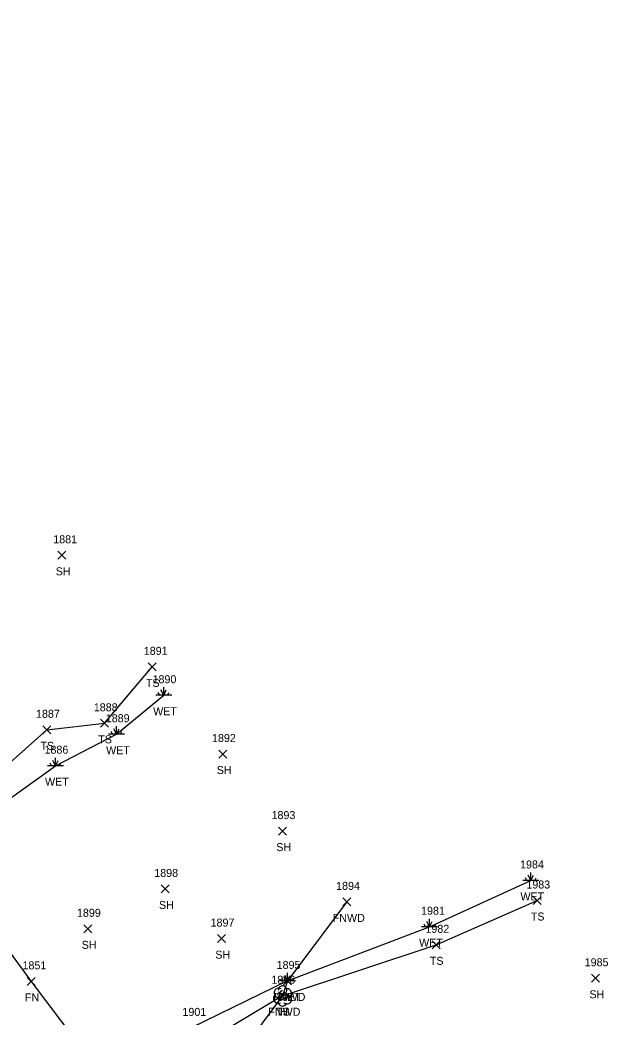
# Model space of a CAD drawing. Extents: x 1501299 to 1502485, y 381423 to 383765.
# Drawn here: x 1501516.8 to 1501663.7, y 383498.2 to 383747.3 of the extents above; entities that cross this region are included whole.
import ezdxf

# ---------------------------------------------------------------- set-up
doc = ezdxf.new("R2010")
doc.units = 0
for name, color, linetype in [('L_A', 7, 'Continuous'), ('L_I', 7, 'Continuous'), ('L_TIC', 7, 'Continuous'), ('LELB', 7, 'Continuous'), ('LFNC', 7, 'Continuous'), ('LTD', 7, 'Continuous'), ('LWET', 7, 'Continuous')]:
    doc.layers.add(name, color=color, linetype=linetype)

msp = doc.modelspace()

# ---------------------------------------------------------------- linework, layer by layer
at = {"layer": 'L_TIC'}
for points in [[(1501526.2, 383612.56), (1501528.2, 383614.56)], [(1501528.2, 383612.56), (1501526.2, 383614.56)], [(1501548.82, 383584.69), (1501550.82, 383586.69)], [(1501550.82, 383584.69), (1501548.82, 383586.69)], [(1501536.91, 383570.58), (1501538.91, 383572.58)], [(1501538.91, 383570.58), (1501536.91, 383572.58)], [(1501522.46, 383568.96), (1501524.46, 383570.96)], [(1501524.46, 383568.96), (1501522.46, 383570.96)], [(1501566.43, 383562.9), (1501568.43, 383564.9)], [(1501568.43, 383562.9), (1501566.43, 383564.9)], [(1501581.3, 383543.65), (1501583.3, 383545.65)], [(1501583.3, 383543.65), (1501581.3, 383545.65)], [(1501552, 383529.2), (1501554, 383531.2)], [(1501554, 383529.2), (1501552, 383531.2)], [(1501597.42, 383525.97), (1501599.42, 383527.97)], [(1501599.42, 383525.97), (1501597.42, 383527.97)], [(1501644.95, 383526.31), (1501646.95, 383528.31)], [(1501646.95, 383526.31), (1501644.95, 383528.31)], [(1501532.7, 383519.24), (1501534.7, 383521.24)], [(1501534.7, 383519.24), (1501532.7, 383521.24)], [(1501566.07, 383516.79), (1501568.07, 383518.79)], [(1501568.07, 383516.79), (1501566.07, 383518.79)], [(1501619.73, 383515.24), (1501621.73, 383517.24)], [(1501621.73, 383515.24), (1501619.73, 383517.24)], [(1501659.51, 383506.88), (1501661.51, 383508.88)], [(1501661.51, 383506.88), (1501659.51, 383508.88)], [(1501518.53, 383506.11), (1501520.53, 383508.11)], [(1501520.53, 383506.11), (1501518.53, 383508.11)], [(1501582.57, 383506.22), (1501584.57, 383508.22)], [(1501584.57, 383506.22), (1501582.57, 383508.22)], [(1501581.32, 383502.52), (1501583.32, 383504.52)], [(1501583.32, 383502.52), (1501581.32, 383504.52)], [(1501581.32, 383502.52), (1501583.32, 383504.52)], [(1501583.32, 383502.52), (1501581.32, 383504.52)], [(1501581.32, 383502.52), (1501583.32, 383504.52)], [(1501583.32, 383502.52), (1501581.32, 383504.52)]]:
    msp.add_lwpolyline(points, dxfattribs=at)
at = {"layer": 'LELB'}
for points in [[(1501492.24, 383541.02), (1501495.83, 383538.88), (1501505.86, 383554.33), (1501523.46, 383569.96), (1501537.91, 383571.58), (1501549.82, 383585.69)], [(1501582.32, 383503.52), (1501620.73, 383516.24), (1501645.95, 383527.31)], [(1501582.32, 383503.52), (1501563.19, 383491.98), (1501548.8, 383485.29), (1501544.05, 383474.54), (1501543.28, 383465.38), (1501557.45, 383442.58)]]:
    msp.add_lwpolyline(points, dxfattribs=at)
at = {"layer": 'LFNC'}
for points in [[(1501374.37, 383742.56), (1501382.94, 383727.21), (1501403.34, 383685.19), (1501409.51, 383674.58), (1501426.09, 383647.98), (1501436.22, 383631.2), (1501450.55, 383610.14), (1501477.09, 383568.96), (1501495.83, 383538.88), (1501500.46, 383533.1), (1501519.53, 383507.11), (1501541.76, 383477.61), (1501544.05, 383474.54), (1501551.42, 383461.96)], [(1501598.42, 383526.97), (1501583.57, 383507.22), (1501582.32, 383503.52), (1501551.42, 383461.96), (1501556.79, 383457.15), (1501570.08, 383443.83), (1501579.66, 383434.51), (1501590.93, 383422.47), (1501618.03, 383406.52), (1501631.82, 383398.73), (1501638.24, 383395.91), (1501648.8, 383391.86), (1501655.59, 383390.21)]]:
    msp.add_lwpolyline(points, dxfattribs=at)
at = {"layer": 'LTD'}
msp.add_line((1501582.32, 383503.52), (1501582.32, 383503.52), dxfattribs=at)
msp.add_line((1501582.32, 383503.52), (1501582.32, 383503.52), dxfattribs=at)
msp.add_arc((1501582.37, 383504.96), 1.05, 335.5272, 180.9563, dxfattribs=at)
for centre, major_axis, ratio, start_param, end_param in [((1501581.24, 383502.81), (0.58, -1.04), 0.959034, 3.141593, 6.283185), ((1501581.53, 383504.19), (1.21, -0.51), 0.895232, 1.570796, 4.712389), ((1501582.11, 383503.98), (-0.208, -0.792), 0.645439, 3.141593, 6.283185), ((1501582.82, 383503.35), (-0.5, 0.667), 0.989748, 3.141593, 6.283185), ((1501583.36, 383504.1), (-1.14, -0.48), 0.949671, 1.570796, 4.712389), ((1501582.32, 383502.02), (0.26, 1.06), 0.942809, 1.570796, 4.712389), ((1501581.86, 383502.77), (-0.625, -0.083), 0.423636, 0, 3.141593), ((1501583.32, 383502.69), (-1.09, 0.79), 0.841452, 1.570796, 4.712389)]:
    msp.add_ellipse(centre, major_axis=major_axis, ratio=ratio, start_param=start_param, end_param=end_param, dxfattribs=at)
at = {"layer": 'LWET'}
for p, q in [((1501554.66, 383578.59), (1501550.66, 383578.59)), ((1501551.66, 383578.59), (1501551.32, 383579.26)), ((1501552.66, 383578.59), (1501551.99, 383579.92)), ((1501552.66, 383578.59), (1501552.66, 383580.59)), ((1501552.66, 383578.59), (1501553.32, 383579.92)), ((1501553.66, 383578.59), (1501553.99, 383579.26)), ((1501542.9, 383568.85), (1501538.9, 383568.85)), ((1501539.9, 383568.85), (1501539.57, 383569.51)), ((1501540.9, 383568.85), (1501540.24, 383570.18)), ((1501540.9, 383568.85), (1501540.9, 383570.85)), ((1501540.9, 383568.85), (1501541.57, 383570.18)), ((1501541.9, 383568.85), (1501542.24, 383569.51)), ((1501524.64, 383560.99), (1501524.31, 383561.65)), ((1501525.64, 383560.99), (1501524.97, 383562.32)), ((1501525.64, 383560.99), (1501525.64, 383562.99)), ((1501525.64, 383560.99), (1501526.31, 383562.32)), ((1501526.64, 383560.99), (1501526.97, 383561.65)), ((1501527.64, 383560.99), (1501523.64, 383560.99)), ((1501644.39, 383532.32), (1501644.39, 383534.32)), ((1501646.39, 383532.32), (1501642.39, 383532.32)), ((1501643.39, 383532.32), (1501643.05, 383532.98)), ((1501644.39, 383532.32), (1501643.72, 383533.65)), ((1501644.39, 383532.32), (1501645.05, 383533.65)), ((1501645.39, 383532.32), (1501645.72, 383532.98)), ((1501618.08, 383520.76), (1501617.74, 383521.42)), ((1501619.08, 383520.76), (1501618.41, 383522.09)), ((1501619.08, 383520.76), (1501619.08, 383522.76)), ((1501619.08, 383520.76), (1501619.74, 383522.09)), ((1501620.08, 383520.76), (1501620.41, 383521.42)), ((1501621.08, 383520.76), (1501617.08, 383520.76)), ((1501583.57, 383507.22), (1501583.57, 383509.22)), ((1501583.57, 383507.22), (1501583.57, 383509.22)), ((1501585.57, 383507.22), (1501581.57, 383507.22)), ((1501585.57, 383507.22), (1501581.57, 383507.22)), ((1501582.57, 383507.22), (1501582.24, 383507.89)), ((1501582.57, 383507.22), (1501582.24, 383507.89)), ((1501583.57, 383507.22), (1501582.91, 383508.56)), ((1501583.57, 383507.22), (1501582.91, 383508.56)), ((1501583.57, 383507.22), (1501584.24, 383508.56)), ((1501583.57, 383507.22), (1501584.24, 383508.56)), ((1501584.57, 383507.22), (1501584.91, 383507.89)), ((1501584.57, 383507.22), (1501584.91, 383507.89))]:
    msp.add_line(p, q, dxfattribs=at)
for points in [[(1501368.35, 383738.78), (1501382.94, 383727.21), (1501398.82, 383737.57), (1501418, 383747.31), (1501440.05, 383727.46), (1501471.68, 383717.46), (1501494.57, 383699.38), (1501486.25, 383674.8), (1501474.27, 383650.63), (1501460.73, 383643.27), (1501445.76, 383639.75), (1501426.09, 383647.98), (1501433.24, 383627.92), (1501444.4, 383608.06), (1501471.74, 383565.71), (1501493.36, 383531.32), (1501500.46, 383533.1), (1501510.21, 383549.97), (1501525.64, 383560.99), (1501540.9, 383568.85), (1501552.66, 383578.59)], [(1501583.57, 383507.22), (1501619.08, 383520.76), (1501644.39, 383532.32)], [(1501583.57, 383507.22), (1501559.55, 383495.49), (1501547.97, 383488.67), (1501541.76, 383477.61), (1501540.15, 383463.77), (1501555.06, 383441.42)]]:
    msp.add_lwpolyline(points, dxfattribs=at)

# ---------------------------------------------------------------- texts
at = {"layer": 'L_A'}
for s, p in [('SH', (1501525.69, 383608.56)), ('TS', (1501548.23, 383580.69)), ('WET', (1501550.03, 383573.59)), ('TS', (1501536.32, 383566.58)), ('TS', (1501521.87, 383564.96)), ('WET', (1501538.28, 383563.85)), ('SH', (1501565.92, 383558.9)), ('WET', (1501523.02, 383555.99)), ('SH', (1501580.78, 383539.65)), ('WET', (1501641.77, 383527.32)), ('SH', (1501551.49, 383525.2)), ('FNWD', (1501594.88, 383521.97)), ('TS', (1501644.36, 383522.31)), ('SH', (1501532.18, 383515.24)), ('WET', (1501616.46, 383515.76)), ('SH', (1501565.56, 383512.79)), ('TS', (1501619.14, 383511.24)), ('FN', (1501518.01, 383502.11)), ('FNWD', (1501580.04, 383502.22)), ('WET', (1501580.95, 383502.22)), ('WET', (1501580.95, 383502.22)), ('SH', (1501659, 383502.88)), ('FNWD', (1501578.79, 383498.52)), ('TS', (1501580.73, 383498.52)), ('TS', (1501580.73, 383498.52)), ('H', (1501581.75, 383498.52))]:
    msp.add_text(s, height=2, dxfattribs=at).set_placement(p)
at = {"layer": 'L_I'}
for s, p in [('1881', (1501525.08, 383616.56)), ('1891', (1501547.69, 383588.69)), ('1890', (1501549.88, 383581.59)), ('1888', (1501535.21, 383574.58)), ('1887', (1501520.77, 383572.96)), ('1889', (1501538.2, 383571.85)), ('1892', (1501564.73, 383566.9)), ('1886', (1501522.89, 383563.99)), ('1893', (1501579.6, 383547.65)), ('1984', (1501641.69, 383535.32)), ('1898', (1501550.31, 383533.2)), ('1894', (1501595.73, 383529.97)), ('1983', (1501643.25, 383530.31)), ('1899', (1501531, 383523.24)), ('1981', (1501616.95, 383523.76)), ('1897', (1501564.38, 383520.79)), ('1982', (1501618.04, 383519.24)), ('1851', (1501517.4, 383510.11)), ('1895', (1501580.88, 383510.22)), ('1895', (1501580.88, 383510.22)), ('1895', (1501580.88, 383510.22)), ('1985', (1501657.82, 383510.88)), ('1896', (1501579.57, 383506.52)), ('1896', (1501579.57, 383506.52)), ('1896', (1501579.57, 383506.52)), ('1896', (1501579.57, 383506.52)), ('1901', (1501557.35, 383498.49))]:
    msp.add_text(s, height=2, dxfattribs=at).set_placement(p)

doc.saveas('drawing.dxf')
